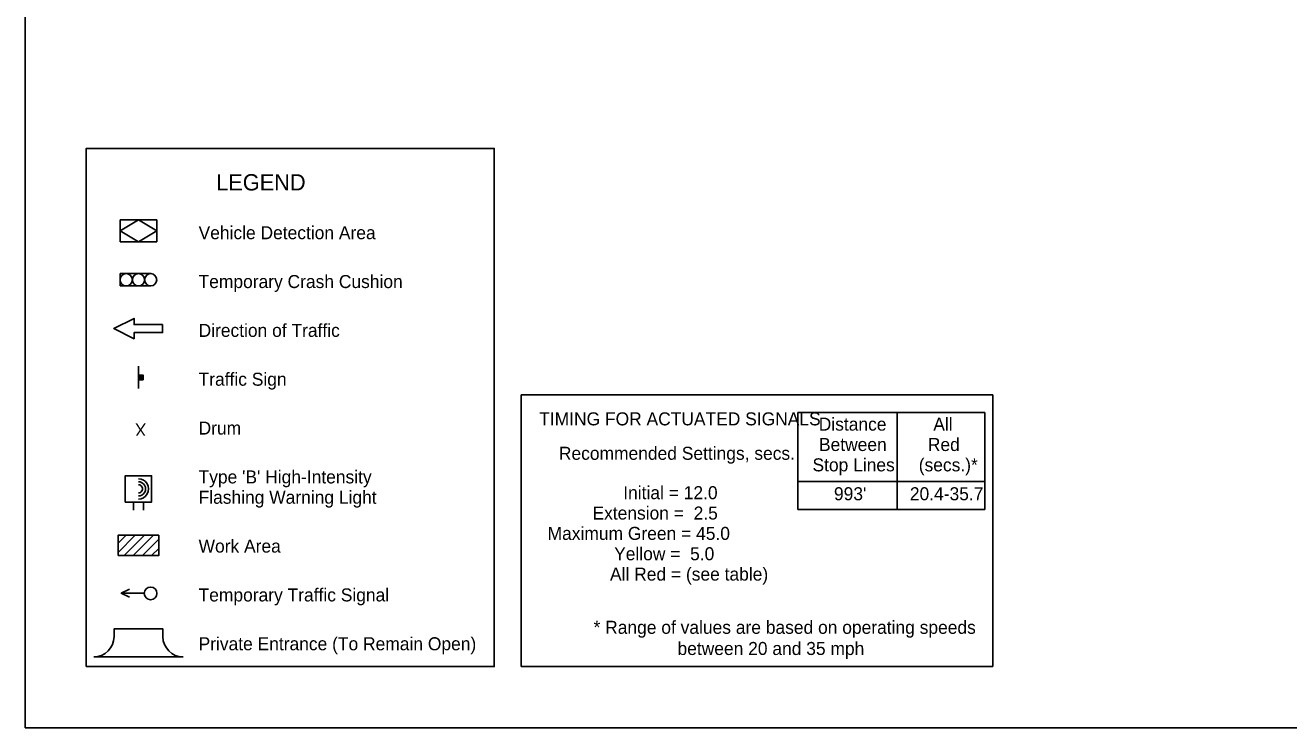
# Model space of a CAD drawing. Extents: x -2134934 to -2127057, y -2139046 to -2137036.
# Drawn here: x -2130232 to -2128679, y -2139046 to -2138183 of the extents above; entities that cross this region are included whole.
import ezdxf

# ---------------------------------------------------------------- set-up
doc = ezdxf.new("R2010")
doc.units = 0
for name, color, linetype in [('BridgeSuperStructureExisting', 7, 'Continuous'), ('Default', 7, 'Continuous'), ('dsnStdLabel', 7, 'Continuous'), ('dsnTextFinalPlan', 7, 'Continuous')]:
    doc.layers.add(name, color=color, linetype=linetype)

msp = doc.modelspace()

# ---------------------------------------------------------------- linework, layer by layer
at = {"layer": 'BridgeSuperStructureExisting'}
for p, q in [((-2130115.3, -2138449.1), (-2130115.3, -2138422.1)), ((-2130115.3, -2138422.1), (-2130070.3, -2138422.1)), ((-2130070.3, -2138449.1), (-2130070.3, -2138422.1)), ((-2130115.3, -2138449.1), (-2130070.3, -2138449.1)), ((-2130115.3, -2138488.1), (-2130115.3, -2138503.1)), ((-2130077.8, -2138488.1), (-2130115.3, -2138488.1)), ((-2130115.3, -2138503.1), (-2130077.8, -2138503.1)), ((-2130092.8, -2138601.9), (-2130092.8, -2138629.4)), ((-2130092.4, -2138618.4), (-2130092.4, -2138612.8)), ((-2130092.1, -2138612.8), (-2130092.1, -2138618.4)), ((-2130091.9, -2138618.4), (-2130091.9, -2138612.8)), ((-2130091.6, -2138612.8), (-2130091.6, -2138618.4)), ((-2130091.4, -2138618.4), (-2130091.4, -2138612.8)), ((-2130091.2, -2138612.8), (-2130091.2, -2138618.4)), ((-2130090.8, -2138618.4), (-2130090.8, -2138612.8)), ((-2130090.6, -2138612.8), (-2130090.6, -2138618.4)), ((-2130090.3, -2138618.4), (-2130090.4, -2138612.8)), ((-2130090, -2138612.8), (-2130090, -2138618.4)), ((-2130089.6, -2138618.4), (-2130089.6, -2138612.8)), ((-2130089.2, -2138612.8), (-2130089.2, -2138618.4)), ((-2130089, -2138618.4), (-2130089, -2138612.8)), ((-2130088.6, -2138612.8), (-2130088.6, -2138618.4)), ((-2130088.3, -2138618.4), (-2130088.3, -2138612.8)), ((-2130088, -2138612.8), (-2130088, -2138618.4)), ((-2130087.8, -2138618.4), (-2130087.8, -2138612.8)), ((-2130087.5, -2138612.8), (-2130087.5, -2138618.4)), ((-2129622.5, -2138636.9), (-2129622.5, -2138970.9)), ((-2129622.5, -2138636.9), (-2129042.5, -2138636.9)), ((-2129042.5, -2138636.9), (-2129042.5, -2138970.9)), ((-2130099.1, -2138768.8), (-2130099.1, -2138778.8)), ((-2130086.6, -2138768.8), (-2130086.6, -2138778.8)), ((-2130117.8, -2138830.5), (-2130096.8, -2138809.5)), ((-2130117.8, -2138819.2), (-2130108.1, -2138809.5)), ((-2130110.5, -2138834.5), (-2130085.5, -2138809.5)), ((-2130099.2, -2138834.5), (-2130074.2, -2138809.5)), ((-2130087.9, -2138834.5), (-2130067.8, -2138814.5)), ((-2130076.6, -2138834.5), (-2130067.8, -2138825.8)), ((-2130085.7, -2138880.6), (-2130113.6, -2138880.6)), ((-2130037.8, -2138959), (-2130147.8, -2138959)), ((-2129622.5, -2138970.9), (-2129042.5, -2138970.9))]:
    msp.add_line(p, q, dxfattribs=at)
for points in [[(-2130157, -2138970.9), (-2129655.4, -2138970.9), (-2129655.4, -2138334.3), (-2130157, -2138334.3)], [(-2130063.1, -2138550.6), (-2130063.1, -2138560.6), (-2130098.1, -2138560.6), (-2130098.1, -2138568.1), (-2130123.1, -2138555.6), (-2130098.1, -2138543.1), (-2130098.1, -2138550.6)], [(-2130092.7, -2138618.4), (-2130092.7, -2138612.7), (-2130087.1, -2138612.7), (-2130087.1, -2138618.4)], [(-2130109.1, -2138768.8), (-2130109.1, -2138736.3), (-2130076.6, -2138736.3), (-2130076.6, -2138768.8)], [(-2130117.8, -2138834.5), (-2130067.8, -2138834.5), (-2130067.8, -2138809.5), (-2130117.8, -2138809.5)]]:
    msp.add_lwpolyline(points, close=True, dxfattribs=at)
for points in [[(-2130104, -2138875.7), (-2130114, -2138880.7), (-2130104, -2138885.7)], [(-2130122.8, -2138934), (-2130122.8, -2138924.5), (-2130062.8, -2138924.5), (-2130062.8, -2138934)]]:
    msp.add_lwpolyline(points, dxfattribs=at)
for centre, radius in [((-2130107.8, -2138495.6), 7.5), ((-2130107.8, -2138495.6), 7.5), ((-2130092.8, -2138495.6), 7.5), ((-2130092.8, -2138495.6), 7.5), ((-2130077.8, -2138495.6), 7.5), ((-2130077.8, -2138495.6), 7.5), ((-2130077.9, -2138880.9), 7.74)]:
    msp.add_circle(centre, radius, dxfattribs=at)
for centre, radius, start, end in [((-2130092.8, -2138752.5), 12.5, 269.4041, 90.5445), ((-2130092.8, -2138752.5), 12.5, 269.4041, 90.5445), ((-2130092.8, -2138752.5), 8.75, 269.4041, 90.5445), ((-2130092.8, -2138752.5), 5, 269.4041, 90.5445), ((-2130147.8, -2138934), 25, 270, 360), ((-2130037.8, -2138934), 25, 180, 270)]:
    msp.add_arc(centre, radius, start, end, dxfattribs=at)
at = {"layer": 'Default'}
msp.add_lwpolyline([(-2130232, -2137035.9), (-2127097, -2137035.9), (-2127097, -2139045.9), (-2130232, -2139045.9)], close=True, dxfattribs=at)
at = {"layer": 'dsnStdLabel'}
for p, q in [((-2129282.5, -2138658.5), (-2129282.5, -2138778)), ((-2129282.5, -2138658.5), (-2129052.5, -2138658.5)), ((-2129160.2, -2138658.5), (-2129160.2, -2138778)), ((-2129052.5, -2138658.5), (-2129052.5, -2138778)), ((-2129282.5, -2138743.5), (-2129052.5, -2138743.5)), ((-2129282.5, -2138778), (-2129052.5, -2138778))]:
    msp.add_line(p, q, dxfattribs=at)
at = {"layer": 'dsnTextFinalPlan'}
msp.add_lwpolyline([(-2130115.3, -2138435.6), (-2130092.8, -2138422.1), (-2130070.3, -2138435.6), (-2130092.8, -2138449.1)], close=True, dxfattribs=at)

# ---------------------------------------------------------------- texts
at = {"layer": 'BridgeSuperStructureExisting'}
msp.add_text('X', height=15, rotation=180, dxfattribs=at).set_placement((-2130083.4, -2138672.2))
at = {"layer": 'dsnStdLabel'}
for s, height, p in [('LEGEND', 20, (-2129997.3, -2138385.9)), ('Vehicle Detection Area', 16, (-2130018.9, -2138445.8)), ('Temporary Crash Cushion', 16, (-2130018.9, -2138505.8)), ('Direction of Traffic', 16, (-2130018.9, -2138565.8)), ('Traffic Sign', 16, (-2130018.9, -2138625.8)), ('Drum', 16, (-2130018.9, -2138685.8)), ('TIMING FOR ACTUATED SIGNALS', 16, (-2129600.2, -2138674.5)), ('Distance', 16, (-2129256.6, -2138681)), ('All', 16, (-2129115.8, -2138681)), ('Recommended Settings, secs.', 16, (-2129576, -2138716.8)), ('Between', 16, (-2129256.3, -2138706)), ('Red', 16, (-2129122.5, -2138706)), ('Stop Lines', 16, (-2129264.3, -2138731)), (' (secs.)*', 16, (-2129139.6, -2138731)), ("Type 'B' High-Intensity", 16, (-2130018.9, -2138745.8)), ('Initial = 12.0', 16, (-2129496.9, -2138765.2)), ('Flashing Warning Light', 16, (-2130018.9, -2138770.8)), ("993'", 16, (-2129237.9, -2138766.5)), ('20.4-35.7', 16, (-2129144.6, -2138766.5)), ('Extension =  2.5', 16, (-2129534.7, -2138790.2)), ('Maximum Green = 45.0', 16, (-2129589.9, -2138815.2)), ('Work Area', 16, (-2130018.9, -2138830.8)), ('Yellow =  5.0', 16, (-2129508.1, -2138840.2)), ('All Red = (see table)', 16, (-2129513.2, -2138865.2)), ('Temporary Traffic Signal', 16, (-2130018.9, -2138890.8)), ('* Range of values are based on operating speeds', 16, (-2129533.4, -2138930.6)), ('Private Entrance (To Remain Open)', 16, (-2130018.9, -2138950.8)), ('between 20 and 35 mph', 16, (-2129430.2, -2138956.6))]:
    msp.add_text(s, height=height, dxfattribs=at).set_placement(p)

doc.saveas('drawing.dxf')
